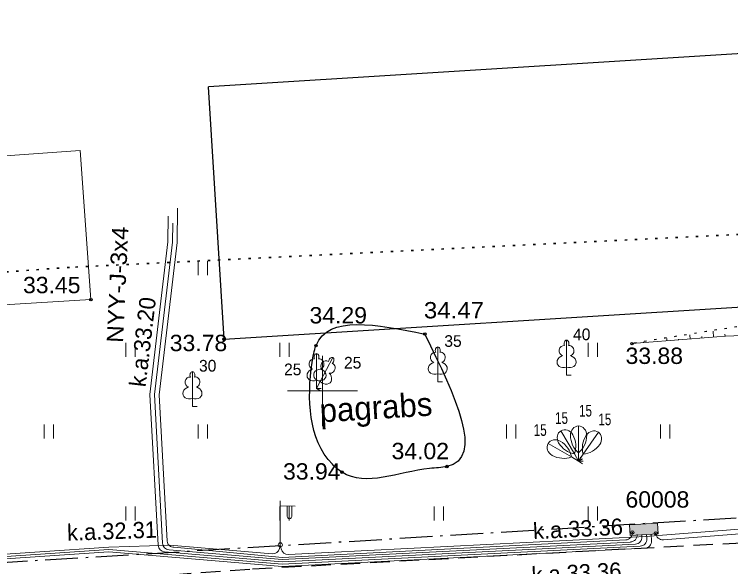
# Model space of a CAD drawing. Extents: x 380758 to 381729, y 283236 to 283533.
# Drawn here: x 381086.8 to 381117.48, y 283342.48 to 283366.12 of the extents above; entities that cross this region are included whole.
import ezdxf

# ---------------------------------------------------------------- set-up
doc = ezdxf.new("R2010")
doc.units = 0
doc.header["$LTSCALE"] = 0.28
doc.header["$PDMODE"] = 32
doc.header["$PDSIZE"] = 0.14
for name, pattern in [('DOT_DASHED', [7.7, 5, -1.2, 0.3, -1.2]), ('DOTTED', [1.5, 0.3, -1.2]), ('MEDIUM_DASHED', [4.5, 3, -1.5])]:
    doc.linetypes.add(name, pattern=pattern)
for name, color, linetype, lineweight in [('1', 7, 'Continuous', 13), ('18', 7, 'Continuous', 13), ('21', 7, 'Continuous', 25), ('23', 7, 'Continuous', 13), ('25', 7, 'DOTTED', 35), ('29', 7, 'DOT_DASHED', 25), ('30', 7, 'Continuous', 13), ('31', 7, 'Continuous', 13), ('37', 7, 'MEDIUM_DASHED', 13), ('39', 7, 'Continuous', 13), ('4', 7, 'Continuous', 13), ('40', 7, 'Continuous', 25), ('44', 7, 'Continuous', 13), ('45', 7, 'Continuous', 13), ('58', 7, 'Continuous', 25), ('7', 7, 'Continuous', 13)]:
    doc.layers.add(name, color=color, linetype=linetype, lineweight=lineweight)

msp = doc.modelspace()

# ---------------------------------------------------------------- hatches: boundary and pattern name
at = {"layer": '18'}
msp.add_hatch(color=256, dxfattribs=at).paths.add_polyline_path([(381113.146, 283344.266), (381114.344, 283344.341), (381114.372, 283343.892), (381113.174, 283343.817)])

# ---------------------------------------------------------------- linework, layer by layer
at = {"layer": '1'}
for p, q in [((381110.448, 283352.173), (381110.448, 283351.02)), ((381104.935, 283351.887), (381104.935, 283350.734)), ((381110.538, 283351.941), (381110.537, 283351.942)), ((381099.743, 283351.601), (381099.743, 283350.448)), ((381105.025, 283351.655), (381105.024, 283351.656)), ((381099.833, 283351.369), (381099.832, 283351.37)), ((381100.444, 283351.427), (381099.905, 283350.408)), ((381100.415, 283351.18), (381100.414, 283351.181)), ((381110.448, 283351.02), (381110.448, 283350.673)), ((381094.431, 283350.829), (381094.431, 283349.676)), ((381094.521, 283350.597), (381094.52, 283350.598)), ((381104.935, 283350.734), (381104.935, 283350.387)), ((381110.448, 283350.673), (381110.648, 283350.673)), ((381099.743, 283350.448), (381099.743, 283350.101)), ((381099.905, 283350.408), (381099.743, 283350.101)), ((381104.935, 283350.387), (381105.135, 283350.387)), ((381099.743, 283350.101), (381099.943, 283350.101)), ((381099.743, 283350.101), (381099.92, 283350.008)), ((381094.431, 283349.676), (381094.431, 283349.329)), ((381094.431, 283349.329), (381094.631, 283349.329)), ((381110.962, 283348.502), (381110.962, 283347.354)), ((381110.211, 283348.301), (381110.786, 283347.307)), ((381111.81, 283348.24), (381111.161, 283347.292)), ((381109.659, 283347.746), (381110.656, 283347.177)), ((381110.656, 283347.177), (381110.962, 283347.002)), ((381110.786, 283347.307), (381110.962, 283347.002)), ((381110.962, 283347.354), (381110.962, 283347.002)), ((381111.161, 283347.292), (381110.962, 283347.002)), ((381110.962, 283347.002), (381111.061, 283347.176)), ((381110.962, 283347.002), (381111.135, 283347.102)), ((381110.962, 283347.002), (381111.162, 283347.002)), ((381110.962, 283347.002), (381111.127, 283346.889))]:
    msp.add_line(p, q, dxfattribs=at)
for centre, major_axis, ratio, start_param, end_param in [((381110.4484, 283352.0231), (0, -0.1499), 0.707107, 3.1453698, 5.2874846), ((381110.4476, 283352.0231), (0, -0.1499), 0.707107, 0.9957007, 3.1378155), ((381104.9354, 283351.7371), (0, -0.1499), 0.707107, 3.1453698, 5.2874846), ((381104.9346, 283351.7371), (0, -0.1499), 0.707107, 0.9957007, 3.1378155), ((381110.3197, 283351.7282), (-0.0387, -0.2124), 0.861323, 3.1415927, 6.2831853), ((381110.5763, 283351.7282), (0.0387, -0.2124), 0.861323, 6.2831853, 9.424778), ((381099.7434, 283351.4511), (0, -0.1499), 0.707107, 3.1453698, 5.2874846), ((381099.7426, 283351.4511), (0, -0.1499), 0.707107, 0.9957007, 3.1378155), ((381104.8067, 283351.4422), (-0.0387, -0.2124), 0.861323, 3.1415927, 6.2831853), ((381105.0633, 283351.4422), (0.0387, -0.2124), 0.861323, 6.2831853, 9.424778), ((381110.3584, 283351.2659), (0.3068, 0.0951), 0.814445, 1.5707963, 4.7520146), ((381110.5376, 283351.2659), (-0.3068, 0.0951), 0.814445, 1.5311707, 4.712389), ((381099.6147, 283351.1562), (-0.0387, -0.2124), 0.861323, 3.1415927, 6.2831853), ((381099.8713, 283351.1562), (0.0387, -0.2124), 0.861323, 6.2831853, 9.424778), ((381100.1228, 283351.0938), (-0.1335, -0.1697), 0.861323, 3.1415927, 6.2831853), ((381100.3744, 283351.2943), (-0.0701, -0.1325), 0.707107, 3.1453698, 5.2874846), ((381100.3497, 283350.9739), (-0.065, -0.2059), 0.861323, 6.2831853, 9.424778), ((381100.3737, 283351.2947), (-0.0701, -0.1325), 0.707107, 0.9957007, 3.1378155), ((381104.8454, 283350.9799), (0.3068, 0.0951), 0.814445, 1.5707963, 4.7520146), ((381105.0246, 283350.9799), (-0.3068, 0.0951), 0.814445, 1.5311707, 4.712389), ((381099.6534, 283350.6939), (0.3068, 0.0951), 0.814445, 1.5707963, 4.7520146), ((381099.941, 283350.667), (0.3157, -0.0593), 0.814445, 1.5707963, 4.7520146), ((381099.8326, 283350.6939), (-0.3068, 0.0951), 0.814445, 1.5311707, 4.712389), ((381094.3027, 283350.3842), (-0.0387, -0.2124), 0.861323, 3.1415927, 6.2831853), ((381094.4314, 283350.6791), (0, -0.1499), 0.707107, 3.1453698, 5.2874846), ((381094.4306, 283350.6791), (0, -0.1499), 0.707107, 0.9957007, 3.1378155), ((381094.5593, 283350.3842), (0.0387, -0.2124), 0.861323, 6.2831853, 9.424778), ((381100.0993, 283350.5833), (-0.2268, 0.2275), 0.814445, 1.5311707, 4.712389), ((381094.3414, 283349.9219), (0.3068, 0.0951), 0.814445, 1.5707963, 4.7520146), ((381094.5206, 283349.9219), (-0.3068, 0.0951), 0.814445, 1.5311707, 4.712389), ((381110.4114, 283347.9543), (0.2002, -0.3463), 0.875, 1.5707963, 3.1415927), ((381110.4114, 283347.9543), (0.2002, -0.3463), 0.875, 1.5707963, 3.1415927), ((381110.962, 283348.102), (0, 0.4), 0.875, 0, 1.5707963), ((381110.962, 283348.102), (0, -0.4), 0.875, 1.5707963, 3.1415927), ((381110.962, 283348.102), (0, -0.4), 0.875, 1.5707963, 3.1415927), ((381110.4114, 283347.9543), (-0.2002, 0.3463), 0.875, 0, 1.5707963), ((381111.4373, 283348.1254), (0, -0.9434), 0.875, 4.7372004, 5.6697113), ((381109.9882, 283347.7366), (0.4722, -0.8167), 0.875, 0.613474, 1.5459849), ((381110.4867, 283348.1254), (0, -0.9434), 0.875, 0.613474, 1.5459849), ((381111.9889, 283347.6603), (-0.5332, -0.7783), 0.875, 4.7372004, 5.6697113), ((381111.5836, 283347.9095), (0.226, 0.33), 0.875, 0, 1.5707963), ((381111.5836, 283347.9095), (0.226, 0.33), 0.875, 4.712389, 6.2831853), ((381111.5836, 283347.9095), (0.226, 0.33), 0.875, 4.712389, 6.2831853), ((381110.0068, 283347.5475), (-0.3474, 0.1984), 0.875, 4.712389, 6.2831853), ((381110.0068, 283347.5475), (-0.3474, 0.1984), 0.875, 4.712389, 6.2831853), ((381110.8111, 283348.2124), (0.4722, -0.8167), 0.875, 4.7372004, 5.6697113), ((381109.7508, 283347.1464), (0.8193, -0.4678), 0.875, 0.613474, 1.5459849), ((381110.0068, 283347.5475), (-0.3474, 0.1984), 0.875, 0, 1.5707963), ((381111.2048, 283348.1974), (-0.5332, -0.7783), 0.875, 0.613474, 1.5459849), ((381110.2221, 283347.9718), (0.8193, -0.4678), 0.875, 4.7372004, 5.6697113)]:
    msp.add_ellipse(centre, major_axis=major_axis, ratio=ratio, start_param=start_param, end_param=end_param, dxfattribs=at)
at = {"layer": '18'}
msp.add_lwpolyline([(381113.146, 283344.266), (381114.344, 283344.341), (381114.372, 283343.892), (381113.174, 283343.817)], close=True, dxfattribs=at)
at = {"layer": '21'}
msp.add_spline([(381104.379, 283352.435), (381099.721, 283351.942), (381099.556, 283351.222), (381100.423, 283346.863), (381100.835, 283346.524), (381104.581, 283346.682), (381105.323, 283346.765), (381104.379, 283352.435)], degree=3, dxfattribs=at)
at = {"layer": '23'}
for p, q in [((381094.677, 283354.961), (381094.677, 283355.561)), ((381095.077, 283354.961), (381095.077, 283355.561)), ((381091.577, 283351.461), (381091.577, 283352.061)), ((381091.977, 283351.461), (381091.977, 283352.061)), ((381098.177, 283351.461), (381098.177, 283352.061)), ((381098.577, 283351.461), (381098.577, 283352.061)), ((381111.377, 283351.461), (381111.377, 283352.061)), ((381111.777, 283351.461), (381111.777, 283352.061)), ((381088.077, 283347.961), (381088.077, 283348.561)), ((381088.477, 283347.961), (381088.477, 283348.561)), ((381094.677, 283347.961), (381094.677, 283348.561)), ((381095.077, 283347.961), (381095.077, 283348.561)), ((381107.877, 283347.961), (381107.877, 283348.561)), ((381108.277, 283347.961), (381108.277, 283348.561)), ((381114.477, 283347.961), (381114.477, 283348.561)), ((381114.877, 283347.961), (381114.877, 283348.561)), ((381091.577, 283344.461), (381091.577, 283345.061)), ((381091.977, 283344.461), (381091.977, 283345.061)), ((381098.177, 283344.461), (381098.177, 283345.061)), ((381098.577, 283344.461), (381098.577, 283345.061)), ((381104.777, 283344.461), (381104.777, 283345.061)), ((381105.177, 283344.461), (381105.177, 283345.061)), ((381111.377, 283344.461), (381111.377, 283345.061)), ((381111.777, 283344.461), (381111.777, 283345.061))]:
    msp.add_line(p, q, dxfattribs=at)
at = {"layer": '25'}
msp.add_lwpolyline([(381378.132, 283376.241), (381330.368, 283370.09), (381282.589, 283365.052), (381241.341, 283362.776), (381227.597, 283363.335), (381201.225, 283361.612), (381131.764, 283357.382), (381089.163, 283355.29), (381056.824, 283352.96), (381046.619, 283367.047), (381043.733, 283420.739)], dxfattribs=at)
at = {"layer": '29'}
msp.add_line((381234.784, 283351.686), (381044.752, 283340.119), dxfattribs=at)
at = {"layer": '30'}
for points in [[(381100, 283351.5), (381100, 283350), (381100, 283348.5)], [(381098.5, 283350), (381100, 283350), (381101.5, 283350)]]:
    msp.add_lwpolyline(points, dxfattribs=at)
at = {"layer": '31'}
for p, q in [((381115.744, 283352.219), (381115.73, 283352.401)), ((381116.741, 283352.297), (381116.721, 283352.555)), ((381117.24, 283352.336), (381117.233, 283352.428)), ((381113.75, 283352.064), (381113.747, 283352.102)), ((381114.249, 283352.103), (381114.248, 283352.118)), ((381114.747, 283352.142), (381114.739, 283352.247)), ((381115.246, 283352.18), (381115.243, 283352.222)), ((381116.243, 283352.258), (381116.238, 283352.325))]:
    msp.add_line(p, q, dxfattribs=at)
at = {"layer": '31', "linetype": 'DOTTED', "lineweight": 25}
msp.add_spline([(381134.207, 283353.645), (381129.502, 283354.054), (381128.81, 283353.986), (381118.938, 283352.911), (381113.252, 283352.025)], degree=3, dxfattribs=at)
at = {"layer": '31'}
msp.add_spline([(381113.252, 283352.025), (381119.062, 283352.478), (381129.352, 283353.253), (381134.207, 283353.645)], degree=3, dxfattribs=at)
at = {"layer": '37', "lineweight": 25}
msp.add_lwpolyline([(381057.591, 283339.033), (381075.94, 283340.852), (381097.005, 283342.39), (381119.536, 283343.592), (381136.671, 283344.454), (381156.115, 283345.485), (381163.151, 283345.848), (381179.391, 283346.671), (381179.402, 283346.957), (381180.543, 283347.053), (381180.574, 283346.748), (381189.023, 283347.214), (381204.943, 283348.182)], dxfattribs=at)
at = {"layer": '39'}
msp.add_lwpolyline([(381072.426, 283359.069), (381072.866, 283352.857), (381090.081, 283353.908), (381089.629, 283360.288)], close=True, dxfattribs=at)
at = {"layer": '40'}
for q in [(381095.113, 283363.017), (381144.505, 283355.256)]:
    msp.add_line((381095.786, 283352.218), q, dxfattribs=at)
msp.add_lwpolyline([(381144.505, 283355.256), (381143.832, 283366.055), (381095.113, 283363.017)], dxfattribs=at)
at = {"layer": '44'}
for p, q in [((381098.193, 283343.413), (381098.193, 283345.296)), ((381098.193, 283345.08), (381098.828, 283345.075)), ((381098.483, 283345.078), (381098.483, 283344.684)), ((381098.693, 283345.076), (381098.693, 283344.684))]:
    msp.add_line(p, q, dxfattribs=at)
msp.add_circle((381098.193, 283343.413), 0.09, dxfattribs=at)
msp.add_ellipse((381098.588, 283344.6835), major_axis=(0, -0.1509), ratio=0.695971, start_param=4.712389, end_param=7.8539816, dxfattribs=at)
at = {"layer": '45'}
msp.add_line((381098.538, 283343.003), (381113.823, 283343.769), dxfattribs=at)
for points in [[(381113.831, 283343.77), (381126.397, 283344.751), (381146.082, 283345.773)], [(381032.402, 283337.854), (381049.394, 283338.981), (381050.924, 283339.056), (381057.172, 283339.986), (381081.97, 283342.714), (381090.848, 283343.32), (381093.46, 283343.399), (381097.843, 283343.028)], [(381098.162, 283343.265), (381098.193, 283343.413), (381098.229, 283343.241)]]:
    msp.add_lwpolyline(points, dxfattribs=at)
for centre, start, end in [((381113.808, 283344.069), 272.86957, 274.46249), ((381097.8681, 283343.3266), 265.1534, 348.04709), ((381098.523, 283343.3029), 191.9529, 272.86956)]:
    msp.add_arc(centre, 0.3, start, end, dxfattribs=at)
at = {"layer": '58'}
for centre in [(381090.081, 283353.9081), (381104.379, 283352.4351), (381095.786, 283352.2181), (381113.252, 283352.0251), (381099.721, 283351.9421), (381100.835, 283346.5241), (381105.323, 283346.7651)]:
    msp.add_circle(centre, 0.0534, dxfattribs=at)
at = {"layer": '7'}
for p, q in [((381113.473, 283343.856), (381113.474, 283343.836)), ((381113.679, 283343.766), (381113.674, 283343.848)), ((381113.885, 283343.676), (381113.873, 283343.861)), ((381114.091, 283343.586), (381114.073, 283343.873))]:
    msp.add_line(p, q, dxfattribs=at)
for points in [[(381093.789, 283357.827), (381093.779, 283356.353), (381093.01, 283349.836), (381093.351, 283343.568)], [(381093.387, 283357.474), (381093.379, 283356.378), (381092.609, 283349.849), (381092.959, 283343.4)], [(381093.585, 283357.184), (381093.579, 283356.366), (381092.81, 283349.843), (381093.155, 283343.484)], [(381114.594, 283343.629), (381126.41, 283344.551), (381146.242, 283345.581), (381153.952, 283346.263), (381170.985, 283346.978), (381183.147, 283347.72)], [(381093.429, 283343.201), (381098.279, 283342.79), (381113.188, 283343.537)], [(381093.639, 283343.315), (381098.283, 283342.88), (381112.982, 283343.627)], [(381050.816, 283338.838), (381057.197, 283339.787), (381081.988, 283342.515), (381090.847, 283343.119), (381098.274, 283342.489), (381113.806, 283343.268)], [(381082.257, 283342.634), (381090.847, 283343.219), (381098.276, 283342.59), (381113.6, 283343.358)], [(381093.234, 283343.117), (381098.277, 283342.69), (381113.394, 283343.448)]]:
    msp.add_lwpolyline(points, dxfattribs=at)
for centre, radius, start, end in [((381112.9674, 283343.9268), 0.3, 272.86957, 3.55283), ((381113.1734, 283343.837), 0.3, 272.86957, 3.55283), ((381114.5704, 283343.9279), 0.3, 183.55283, 274.46248), ((381093.4547, 283343.5001), 0.3, 183.11, 265.1534), ((381093.6203, 283343.5837), 0.2699, 183.42552, 273.87888), ((381113.3793, 283343.7472), 0.3, 272.86957, 3.55283), ((381113.5853, 283343.6574), 0.3, 272.86957, 3.55283), ((381113.7913, 283343.5676), 0.3, 272.86957, 3.55283), ((381093.2589, 283343.4164), 0.3, 183.11, 265.1534)]:
    msp.add_arc(centre, radius, start, end, dxfattribs=at)
for p in [(381113.267, 283343.945), (381114.271, 283343.909)]:
    msp.add_point(p, dxfattribs=at)

# ---------------------------------------------------------------- texts
at = {"layer": '1'}
for s, p in [('35', (381105.215, 283351.887)), ('40', (381110.728, 283352.173)), ('25', (381100.919, 283350.959)), ('30', (381094.711, 283350.829)), ('25', (381098.353, 283350.673))]:
    msp.add_text(s, height=0.5, dxfattribs=at).set_placement(p)
at = {"layer": '1', "width": 0.75}
for p in [(381110.981, 283348.906), (381109.954, 283348.592), (381111.808, 283348.535), (381109.042, 283348.078)]:
    msp.add_text('15', height=0.5, dxfattribs=at).set_placement(p)
at = {"layer": '4'}
msp.add_text('pagrabs', height=1, rotation=3.568, dxfattribs=at).set_placement((381099.905, 283348.651))
at = {"layer": '45'}
for s, rotation, p in [('k.a.32.31', 2.015, (381089.073, 283343.589)), ('k.a.33.36', 2.932, (381108.968, 283341.775))]:
    msp.add_text(s, height=0.7, rotation=rotation, dxfattribs=at).set_placement(p)
at = {"layer": '58'}
for s, width, p in [('33.45', 1.05, (381087.177, 283354.184)), ('34.47', 1.1, (381104.339, 283353.105)), ('34.29', 1.05, (381099.444, 283352.889)), ('33.78', 1.05, (381093.459, 283351.704)), ('33.88', 1.05, (381112.975, 283351.156)), ('34.02', 1.05, (381102.956, 283347.08)), ('33.94', 1.05, (381098.31, 283346.208))]:
    msp.add_text(s, height=0.7, dxfattribs=dict(at, width=width)).set_placement(p)
at = {"layer": '7', "width": 1.1}
msp.add_text('NYY-J-3x4', height=0.7, rotation=87.311, dxfattribs=at).set_placement((381091.457, 283352.05))
at = {"layer": '7'}
for s, rotation, p in [('k.a.33.20', 83.274, (381092.421, 283350.145)), ('k.a.33.36', 2.932, (381109.03, 283343.655))]:
    msp.add_text(s, height=0.7, rotation=rotation, dxfattribs=at).set_placement(p)
at = {"layer": '7', "width": 1.05}
msp.add_text('60008', height=0.7, dxfattribs=at).set_placement((381112.972, 283345.008))

doc.saveas('drawing.dxf')
